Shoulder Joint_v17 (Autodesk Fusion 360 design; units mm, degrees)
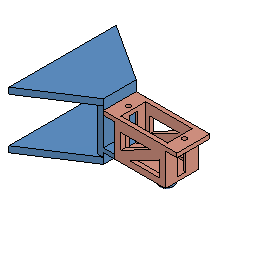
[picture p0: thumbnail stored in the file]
component_insert "Component Insert"
sketch "Sketch1" plane through (0, 0, 15.8) normal (0, 0, -1) x axis (1, 0, 0)
  line L1 (-18, 8.05) -> (-12.4, 8.05)
  line L2 (-18, -8.05) -> (-18, 8.05)
  line L3 (-13.4, -8.05) -> (-18, -8.05)
  line L4 (-11.4, -1.975) -> (-12.4, -1.975)
  line L5 (-12.4, 2.025) -> (-11.4, 2.025)
  line L6 (-21, 8.05) -> (-18, 8.05)
  line L7 (-21, -8.05) -> (-21, 8.05)
  line L8 (-18, -8.05) -> (-21, -8.05)
  line L9 (-18, 8.05) -> (-18, -8.05)
  line L10 (-11.4, 2.025) -> (-11.4, -1.975)
  line L11 (-12.4, 8.05) -> (-12.4, 2.025)
  line L12 (-13.4, -8.0479) -> (-13.4, -8.05)
  line L13 (-12.4, -8.0479) -> (-13.4, -8.0479)
  line L14 (-12.4, -1.975) -> (-12.4, -8.0479)
  circle C1 centre (-13.7, 0) radius 1.1
  point P5 (-18, 8.05)
  point P11 (-18, 8.05)
  point P12 (-21, 8.05)
  point P13 (-21, -8.05)
  horizontal L6
  vertical L7
  horizontal L8
  vertical L9
  coincident P5 P11
  dimension "d1" distance P11 P12 = 3
  dimension "d23" distance P12 P13 = 16.1
extrude "Extrude1" new body sketch "Sketch1" profile of L2 L6 L7 L8 L9 along normal blind 20.8 (= "15.8 mm + 5 mm")
extrude "Extrude2" add of existing geometry blind 7 (= "2 mm + 5 mm")
sketch "Sketch3" plane through (-21, 0, 0) normal (-1, 0, 0) x axis (0, -1, 0)
  line L1 (-8.05, -5) -> (-8.05, 22.8)
  line L2 (8.05, -5) -> (-8.05, -5)
  line L3 (8.05, 22.8) -> (8.05, -5)
  line L4 (-8.05, 22.8) -> (8.05, 22.8)
  line L5 (8.05, 22.8) -> (-8.05, 22.8)
  line L6 (8.05, 19.8) -> (8.05, 22.8)
  line L7 (-8.05, 19.8) -> (8.05, 19.8)
  line L8 (-8.05, 22.8) -> (-8.05, 19.8)
  line L9 (8.05, -5) -> (-8.05, -5)
  line L10 (8.05, -2) -> (8.05, -5)
  line L11 (-8.05, -2) -> (8.05, -2)
  line L12 (-8.05, -5) -> (-8.05, -2)
  point P2 (-8.05, 22.8)
  point P6 (-8.05, 22.8)
  point P3 (-8.05, -5)
  point P10 (-8.05, -5)
  point P9 (-8.05, 19.8)
  point P13 (-8.05, -2)
  point P7 (8.05, 22.8)
  point P11 (8.05, -5)
  horizontal L5
  vertical L6
  horizontal L7
  vertical L8
  coincident P2 P6
  horizontal L9
  vertical L10
  horizontal L11
  vertical L12
  coincident P3 P10
  dimension "d10" distance P6 P9 = 3
  dimension "d11" distance P10 P13 = 3
  dimension "d24" distance P6 P7 = 16.1
  dimension "d25" distance P10 P11 = 16.1 (= "d24")
extrude "Extrude4" add sketch "Sketch3" along normal blind 25
sketch "Sketch4" plane through (0, 0, 0) normal (0, 0, -1) x axis (1, 0, 0)
  line L1 (12.4, -8.0479) -> (-12.4, -8.0479)
  line L2 (-12.4, 8.05) -> (12.4, 8.05)
  line L3 (12.4, 8.05) -> (12.4, -8.0479)
  line L4 (-12.4, -8.0479) -> (-12.4, 8.05)
  circle C1 centre (4.9, 0) radius 3.5
  dimension "d17" diameter C1 = 7
extrude "Extrude5" new body sketch "Sketch4" profile of C1 along normal blind 6
sketch "Sketch5" plane through (-12.4, 0, 0) normal (-1, 0, 0) x axis (0, -1, 0)
  line L1 (-1.975, 15.8) -> (-1.975, 2)
  line L2 (-8.0479, 15.8) -> (-1.975, 15.8)
  line L3 (-8.0479, 0) -> (-8.0479, 15.8)
  line L4 (8.05, 0) -> (-8.0479, 0)
  line L5 (8.05, 15.8) -> (8.05, 0)
  line L6 (2.025, 15.8) -> (8.05, 15.8)
  line L7 (2.025, 2) -> (2.025, 15.8)
  line L8 (-1.975, 2) -> (2.025, 2)
  line L9 (-8.05, 0) -> (8.05, 0)
  line L10 (-8.05, 2) -> (-8.05, 0)
  line L11 (8.05, 2) -> (-8.05, 2)
  line L12 (8.05, 0) -> (8.05, 2)
  point P6 (8.05, 0)
  point P10 (8.05, 0)
  point P11 (-8.05, 0)
  point P13 (8.05, 2)
  horizontal L9
  vertical L10
  horizontal L11
  vertical L12
  coincident P6 P10
  dimension "d26" distance P10 P11 = 16.1
  dimension "d27" distance P10 P13 = 2
extrude "Extrude7" add sketch "Sketch5" profile of L3 L4 L5 L8 L9 L11 L12 along normal blind 5.6 (= "3.6 mm + 2 mm")
fillet "Fillet3" radius 1
sketch "Sketch7" plane through (0, -8.05, 0) normal (0, -1, 0) x axis (1, 0, 0)
  line L1 (-21, -2) -> (-21, 19.8)
  line L2 (-46, -2) -> (-21, -2)
  line L3 (-46, -5) -> (-46, -2)
  line L4 (-18, -5) -> (-46, -5)
  line L5 (-18, 0) -> (-18, -5)
  line L6 (-12.4, 0) -> (-18, 0)
  line L7 (-12.4, 2) -> (-12.4, 0)
  line L8 (-18, 2) -> (-12.4, 2)
  line L9 (-18, 22.8) -> (-18, 2)
  line L10 (-46, 22.8) -> (-18, 22.8)
  line L11 (-46, 19.8) -> (-46, 22.8)
  line L12 (-21, 19.8) -> (-46, 19.8)
  line L13 (-46, -5) -> (-18, -5)
  line L14 (-46, -2) -> (-46, -5)
  line L15 (-18, -2) -> (-46, -2)
  line L16 (-18, -5) -> (-18, -2)
  point P4 (-46, -2)
  point P16 (-46, -2)
  point P6 (-18, -5)
  point P14 (-18, -5)
  horizontal L13
  vertical L14
  horizontal L15
  vertical L16
  coincident P4 P16
  coincident P6 P14
extrude "Extrude8" add sketch "Sketch7" profile of L2 L3 L4 L5 L13 L14 L15 L16 along normal blind 25
sketch "Sketch8" plane through (0, 0, -5) normal (0, 0, -1) x axis (1, 0, 0)
  line L1 (-18, 33.05) -> (-18, -8.05)
  line L2 (-46, 33.05) -> (-18, 33.05)
  line L3 (-46, -8.05) -> (-46, 33.05)
  line L4 (-18, -8.05) -> (-46, -8.05)
  line L5 (-18, 33.05) -> (-46, 33.05)
  line L6 (-18, 8.05) -> (-18, 33.05)
  line L7 (-46, 8.05) -> (-18, 8.05)
  line L8 (-46, 33.05) -> (-46, 8.05)
  line L9 (-46, 26.2131) -> (-18, 8.05)
  point P4 (-46, 33.05)
  point P6 (-46, 33.05)
  point P10 (-46, 26.2131)
  point P9 (-46, 8.05)
  horizontal L5
  vertical L6
  horizontal L7
  vertical L8
  coincident P4 P6
  coincident L8 P10
  dimension "d36" distance P6 P9 = 25
extrude "Extrude9" cut sketch "Sketch8" profile of L1 L2 L3 L5 L6 L8 L9 against normal blind 3
work_plane "WorkPlane1" AlongDistance 8.9 (= "( 17.8 / 2 ) * 1 mm")
mirror "Mirror1" mirrorStitchTolerance 0.1
mirror "Mirror2" mirrorStitchTolerance 0.1
mirror "Mirror3" mirrorStitchTolerance 0.1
